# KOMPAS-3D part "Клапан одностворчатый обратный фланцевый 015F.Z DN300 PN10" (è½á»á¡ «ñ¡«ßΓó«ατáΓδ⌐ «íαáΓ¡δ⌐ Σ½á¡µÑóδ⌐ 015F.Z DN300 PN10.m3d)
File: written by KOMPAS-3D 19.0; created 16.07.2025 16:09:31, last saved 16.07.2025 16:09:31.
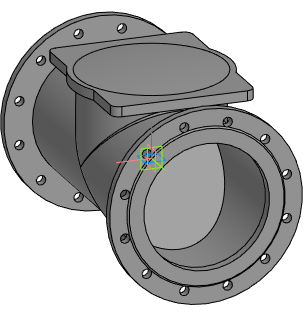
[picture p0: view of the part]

Document properties: Полное имя файла: E:\Dendor Работа Сачек\3D для проектировщиков\5.4 Тип 015F.Z. Клапан одностворчатый обратный фланцевый\stp_Клапан одностворчатый обратный фланцевый 015F.Z PN10_16\Клапан одностворчатый обратный фланцевый 015F.Z DN300 PN10.m3d

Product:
- Part/product: Клапан одностворчатый обратный фланцевый 015F.Z DN300 PN10

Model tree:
1. Операция без истории:1  (labels: Клапан одностворчатый обратный фланцевый 015F.Z DN300 PN10)
2. Операция без истории:2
